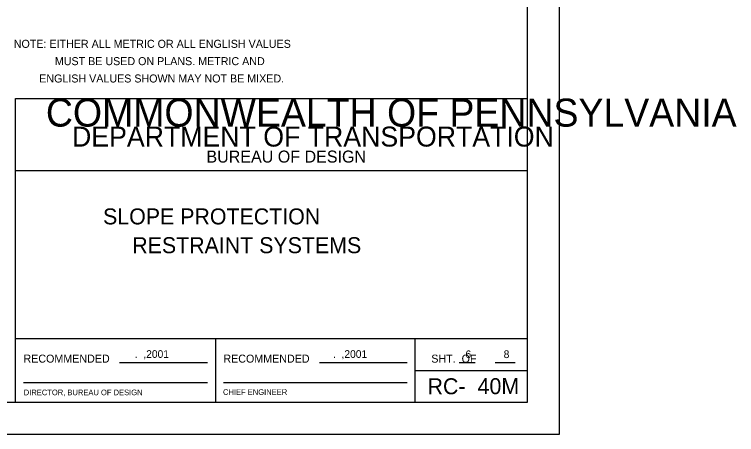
# Model space of a CAD drawing. Extents: x 638850 to 644908, y 297188 to 298900.
# Drawn here: x 642012.2 to 642317.4, y 297277.3 to 297454.8 of the extents above; entities that cross this region are included whole.
import ezdxf

# ---------------------------------------------------------------- set-up
doc = ezdxf.new("R2010")
doc.units = 0
doc.layers.add('1', color=7, linetype='Continuous')
doc.layers.add('3', color=7, linetype='Continuous')

msp = doc.modelspace()

# ---------------------------------------------------------------- linework, layer by layer
at = {"layer": '1'}
for p, q in [((642242.46, 297871.34), (642242.46, 297277.34)), ((642228.96, 297857.84), (642228.96, 297290.84)), ((642012.64, 297290.84), (642012.64, 297419.27)), ((642012.64, 297419.27), (642228.96, 297419.27)), ((642012.64, 297388.85), (642228.96, 297388.85)), ((642012.64, 297317.86), (642228.96, 297317.86)), ((642097.13, 297317.86), (642097.13, 297290.84)), ((642181.64, 297290.84), (642181.64, 297317.86)), ((642056.58, 297307.72), (642093.77, 297307.72)), ((642141.09, 297307.72), (642178.26, 297307.72)), ((642200.24, 297307.72), (642206.98, 297307.72)), ((642215.43, 297307.72), (642222.2, 297307.72)), ((642222.2, 297307.72), (642223.89, 297307.72)), ((642181.64, 297304.34), (642228.96, 297304.34)), ((642016.02, 297299.29), (642093.77, 297299.29)), ((642100.51, 297299.29), (642178.26, 297299.29)), ((642228.96, 297290.84), (641310.96, 297290.84)), ((642242.46, 297277.34), (641270.46, 297277.34))]:
    msp.add_line(p, q, dxfattribs=at)

# ---------------------------------------------------------------- texts
for s, height, p in [('COMMONWEALTH OF PENNSYLVANIA', 11.8354, (642025.5, 297407.43)), ('DEPARTMENT OF TRANSPORTATION', 8.434, (642036.55, 297399)), ('BUREAU OF DESIGN', 5.073, (642093.36, 297392.23)), ('    SLOPE PROTECTION    ', 6.75, (642039.63, 297366.12)), (' RESTRAINT SYSTEMS', 6.75, (642059.49, 297353.96)), ('   .  ,2001', 3.24, (642059.46, 297309.73)), ('   .  ,2001', 3.24, (642143.23, 297309.73)), ('6', 3.24, (642202.85, 297309.65)), ('8', 3.24, (642218.99, 297309.65)), ('RECOMMENDED', 3.3826, (642016.03, 297307.72)), ('RECOMMENDED', 3.3826, (642100.52, 297307.72)), ('SHT.  OF', 3.383, (642188.4, 297307.72)), ('APPROVED', 0.0211, (642058.29, 297307.66)), ('RC-', 6.75, (642186.82, 297294.37)), ('40M', 6.75, (642207.97, 297294.41)), ('DIRECTOR, BUREAU OF DESIGN', 2.3867, (642016.16, 297293.95)), ('CHIEF ENGINEER', 2.387, (642100.36, 297294.11))]:
    msp.add_text(s, height=height, dxfattribs=at).set_placement(p)
at = {"layer": '3'}
for s, p in [('NOTE: EITHER ALL METRIC OR ALL ENGLISH VALUES', (642011.92, 297440.71)), (' MUST BE USED ON PLANS. METRIC AND ', (642028.04, 297433.39)), ('    ENGLISH VALUES SHOWN MAY NOT BE MIXED.', (642017.64, 297426.07))]:
    msp.add_text(s, height=3.3818, dxfattribs=at).set_placement(p)

doc.saveas('drawing.dxf')
